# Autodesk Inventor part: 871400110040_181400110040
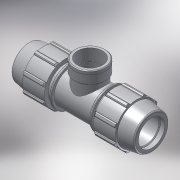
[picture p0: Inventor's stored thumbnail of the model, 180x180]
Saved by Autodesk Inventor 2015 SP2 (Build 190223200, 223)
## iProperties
Created: 2017-02
Part Number: 871400110040_181400110040
Material: PVC-Piping
Description: PLASSON TEE WITH THREADED FEMALE OFFTAKE 110-4"-110
Document SubType Name: Modeling
Designer: KIM
Mass: 92.6774 g
Surface Area: 199.44 cm^2
Volume: 66.1981 cm^3
Density: 1.4 g/cm^3
Appearance: Smooth - White
Author: KIM
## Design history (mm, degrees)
derived "87140.ipt"
feature "Solid1::87140.ipt"
feature "Solid2::87140.ipt"
tag "TaggingFeature1"
body "Solid1"
other parameters: "d4" = 21.5, "d5" = 61.92, "d7" = 181, "d11" = 8.6, "d13" = 120 deg, "d14" = 143, "d15" = 10 deg, "d16" = 157.47, "d18" = 5.5, "d19" = 35 deg, "d20" = 17.5 deg, "d21" = 168.33, "d23" = 0, "d25" = 360 deg, "d27" = 3.62, "d33" = 2.2, "d42" = 92.88, "d43" = 5.43, "d46" = 3.3, "d68" = 15.48, "d76" = 110.072, "d80" = 3.30216, "d91" = 135.75, "d95" = 99, "d112" = 52, "d115" = 137.59, "d116" = 135 deg, "d117" = 126.5828, "d118" = 516, "d119" = 99, "d121" = 0, "d122" = 99, "d124" = 0, "d128" = 0, "d129" = 11, "d130" = 15.6, "d131" = 0.3, "d132" = 0.3, "d133" = 137.59, "E_" = 181, "l_2" = 52, "Rp_" = 110.072, "H_" = 516
